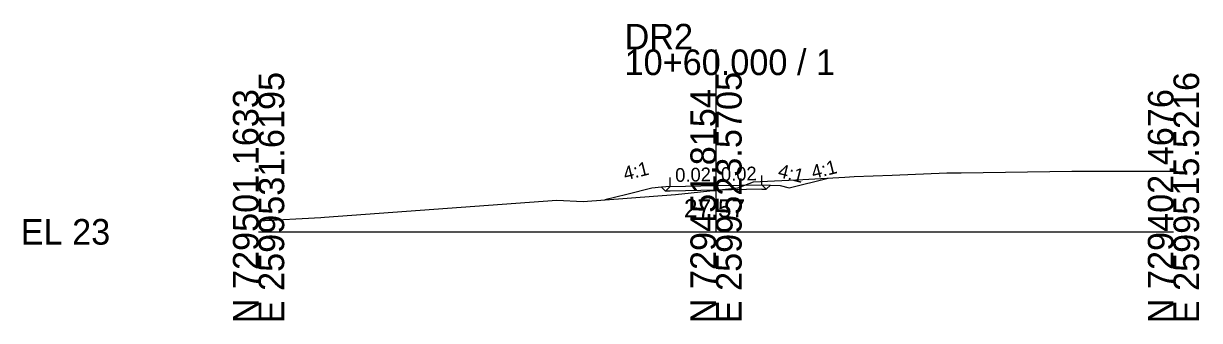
# Model space of a CAD drawing. Extents: x -26 to 1162, y -10 to 9515.
# Drawn here: x -25.7 to 102.8, y 2990.3 to 3022.8 of the extents above; entities that cross this region are included whole.
import ezdxf

# ---------------------------------------------------------------- set-up
doc = ezdxf.new("R2010")
doc.units = 0
for name, color, linetype in [('Exist Cross Section Cell', 7, 'Continuous'), ('Exist XS Center Line Elevation Label', 7, 'Continuous'), ('Exist XS Ground Line', 7, 'Continuous'), ('Prop XS Ditch Slope Text', 7, 'Continuous'), ('Prop XS Dump Level', 7, 'Continuous'), ('Prop XS EOT Tick Mark', 7, 'Continuous'), ('Prop XS Finish Grade', 7, 'Continuous'), ('Prop XS Finish Grade Earthwork', 7, 'Continuous'), ('Prop XS Finish Grade Pavement', 7, 'Continuous'), ('Prop XS Pvmt Edge Slope', 7, 'Continuous'), ('Prop XS SE Text', 7, 'Continuous'), ('Prop XS Side Slope Text', 7, 'Continuous'), ('Prop XS Subgrade Earthwork', 7, 'Continuous')]:
    doc.layers.add(name, color=color, linetype=linetype)

msp = doc.modelspace()

# ---------------------------------------------------------------- linework, layer by layer
at = {"layer": 'Exist Cross Section Cell'}
for p, q in [((50, 3000), (50, 3019.94)), ((0, 3000), (50, 3000)), ((50, 3000), (100, 3000))]:
    msp.add_line(p, q, dxfattribs=at)
at = {"layer": 'Exist XS Ground Line'}
msp.add_lwpolyline([(0, 3001.2), (6.82, 3001.56), (7.21, 3001.59), (32.59, 3003.46), (35.46, 3003.32), (45.57, 3004.08), (50, 3004.57), (52.39, 3004.83), (54.09, 3005.48), (59.47, 3005.71), (64.06, 3005.99), (65.1, 3006.05), (69.25, 3006.2), (75.21, 3006.45), (76.8, 3006.44), (88.88, 3006.65), (89.6, 3006.65), (100, 3006.63)], dxfattribs=at)
at = {"layer": 'Prop XS Dump Level'}
for p, q in [((50, 3005.05), (55, 3005.15)), ((45, 3004.95), (50, 3005.05))]:
    msp.add_line(p, q, dxfattribs=at)
at = {"layer": 'Prop XS EOT Tick Mark'}
for p, q in [((45, 3004.95), (45, 3005.95)), ((55, 3005.15), (55, 3006.15))]:
    msp.add_line(p, q, dxfattribs=at)
at = {"layer": 'Prop XS Finish Grade'}
for p, q in [((55, 3005.15), (55.95, 3005.11)), ((45, 3004.95), (44.05, 3004.87))]:
    msp.add_line(p, q, dxfattribs=at)
at = {"layer": 'Prop XS Finish Grade Earthwork'}
for p, q in [((55.95, 3005.11), (57, 3005.07)), ((58, 3004.82), (62.25, 3005.88)), ((40.24, 3004.1), (37.86, 3003.5)), ((43, 3004.79), (40.24, 3004.1)), ((44.05, 3004.87), (43, 3004.79)), ((57, 3005.07), (58, 3004.82))]:
    msp.add_line(p, q, dxfattribs=at)
at = {"layer": 'Prop XS Finish Grade Pavement'}
for p, q in [((50, 3005.05), (55, 3005.15)), ((45, 3004.95), (50, 3005.05))]:
    msp.add_line(p, q, dxfattribs=at)
at = {"layer": 'Prop XS Pvmt Edge Slope'}
for p, q in [((55, 3005.15), (55.49, 3004.66)), ((55.49, 3004.66), (55.95, 3005.11)), ((44.49, 3004.44), (44.05, 3004.87)), ((45, 3004.95), (44.49, 3004.44))]:
    msp.add_line(p, q, dxfattribs=at)
at = {"layer": 'Prop XS Subgrade Earthwork'}
for p, q in [((55.49, 3004.66), (55.95, 3005.11)), ((44.49, 3004.44), (44.05, 3004.87)), ((45, 3004.45), (44.49, 3004.44)), ((50, 3004.55), (45, 3004.45)), ((55, 3004.65), (50, 3004.55)), ((55, 3004.65), (55.49, 3004.66))]:
    msp.add_line(p, q, dxfattribs=at)

# ---------------------------------------------------------------- texts
at = {"layer": 'Exist Cross Section Cell'}
for s, p in [('DR2', (40, 3019.94)), ('10+60.000 / 1', (40, 3017.14)), ('EL 23', (-26, 2998.6))]:
    msp.add_text(s, height=2.8, dxfattribs=at).set_placement(p)
for s, p in [('E 2599531.6195', (2.8, 2990)), ('E 2599523.5705', (52.8, 2990)), ('E 2599515.5216', (102.8, 2990)), ('N 729501.1633', (0, 2990)), ('N 729451.8154', (50, 2990)), ('N 729402.4676', (100, 2990))]:
    msp.add_text(s, height=2.8, rotation=90, dxfattribs=at).set_placement(p)
at = {"layer": 'Exist XS Center Line Elevation Label'}
msp.add_text('27.57', height=2, dxfattribs=at).set_placement((46.49, 3001.57))
at = {"layer": 'Prop XS Ditch Slope Text'}
msp.add_text('4:1', height=1.5, rotation=345.9638, dxfattribs=at).set_placement((56.67, 3006.01))
at = {"layer": 'Prop XS Dump Level'}
for p in [(43, 3004.75), (57, 3005.03)]:
    msp.add_text('Case1', height=0.04, dxfattribs=at).set_placement(p)
at = {"layer": 'Prop XS SE Text'}
for p in [(45.55, 3005.46), (50.55, 3005.56)]:
    msp.add_text('0.02', height=1.5, rotation=1.1458, dxfattribs=at).set_placement(p)
at = {"layer": 'Prop XS Side Slope Text'}
for p in [(60.63, 3005.77), (40.07, 3005.6)]:
    msp.add_text('4:1', height=1.5, rotation=14.0362, dxfattribs=at).set_placement(p)

doc.saveas('drawing.dxf')
